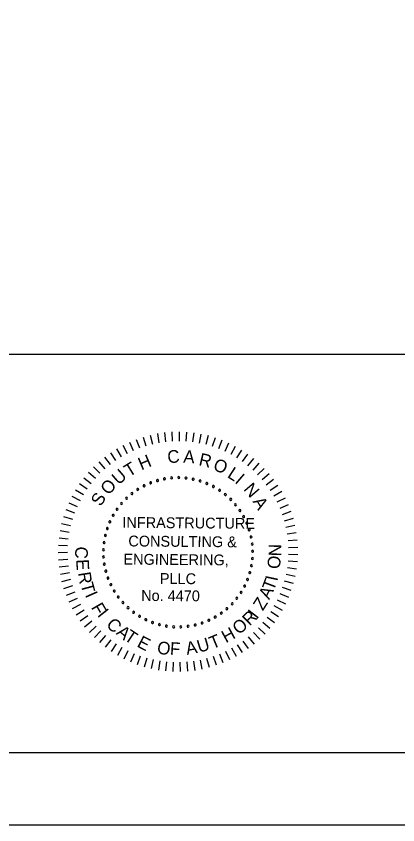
# Model space of a CAD drawing. Extents: x -121.2 to -24.9, y 6.4 to 65.9.
# Drawn here: x -53.92 to -46.89, y 6.35 to 21.24 of the extents above; entities that cross this region are included whole.
import ezdxf

# ---------------------------------------------------------------- set-up
doc = ezdxf.new("R2010")
doc.units = 0
for name, color, linetype in [('BR_BORDER LINES', 7, 'Continuous'), ('BR_TEXT', 7, 'Continuous'), ('Level 31', 7, 'Continuous')]:
    doc.layers.add(name, color=color, linetype=linetype)

msp = doc.modelspace()

# ---------------------------------------------------------------- linework, layer by layer
at = {"layer": 'BR_BORDER LINES'}
for p, q in [((-60.804, 15.017), (-46.496, 15.017)), ((-116.272, 7.683), (-26.496, 7.683))]:
    msp.add_line(p, q, dxfattribs=at)
at = {"layer": 'BR_TEXT'}
for p, q in [((-51.321, 13.553), (-51.292, 13.386)), ((-51.188, 13.572), (-51.169, 13.403)), ((-51.054, 13.583), (-51.045, 13.413)), ((-50.919, 13.586), (-50.921, 13.416)), ((-50.785, 13.58), (-50.796, 13.411)), ((-50.651, 13.567), (-50.673, 13.399)), ((-51.711, 13.447), (-51.651, 13.288)), ((-51.583, 13.49), (-51.533, 13.328)), ((-51.453, 13.526), (-51.413, 13.36)), ((-50.518, 13.545), (-50.55, 13.378)), ((-50.387, 13.515), (-50.429, 13.351)), ((-50.257, 13.478), (-50.31, 13.316)), ((-50.131, 13.432), (-50.193, 13.274)), ((-52.074, 13.272), (-51.987, 13.127)), ((-51.957, 13.338), (-51.878, 13.187)), ((-51.835, 13.396), (-51.766, 13.241)), ((-50.007, 13.379), (-50.079, 13.225)), ((-49.887, 13.318), (-49.968, 13.169)), ((-49.77, 13.251), (-49.86, 13.106)), ((-52.296, 13.12), (-52.192, 12.986)), ((-52.187, 13.2), (-52.091, 13.06)), ((-49.659, 13.176), (-49.757, 13.037)), ((-52.4, 13.034), (-52.287, 12.907)), ((-49.551, 13.094), (-49.658, 12.962)), ((-49.449, 13.006), (-49.564, 12.881)), ((-52.59, 12.844), (-52.463, 12.732)), ((-52.498, 12.942), (-52.378, 12.822)), ((-49.353, 12.913), (-49.475, 12.794)), ((-49.262, 12.813), (-49.391, 12.702)), ((-52.677, 12.741), (-52.543, 12.636)), ((-49.178, 12.708), (-49.313, 12.606)), ((-52.83, 12.52), (-52.684, 12.432)), ((-52.757, 12.633), (-52.617, 12.536)), ((-49.1, 12.598), (-49.242, 12.504)), ((-52.896, 12.402), (-52.745, 12.324)), ((-49.029, 12.484), (-49.176, 12.398)), ((-48.966, 12.365), (-49.117, 12.289)), ((-52.954, 12.281), (-52.799, 12.212)), ((-48.909, 12.243), (-49.065, 12.176)), ((-53.006, 12.157), (-52.847, 12.097)), ((-48.86, 12.117), (-49.02, 12.06)), ((-53.049, 12.029), (-52.887, 11.98)), ((-48.819, 11.989), (-48.982, 11.942)), ((-53.113, 11.768), (-52.946, 11.738)), ((-53.085, 11.9), (-52.92, 11.86)), ((-48.786, 11.859), (-48.951, 11.822)), ((-53.132, 11.635), (-52.964, 11.615)), ((-48.76, 11.727), (-48.928, 11.7)), ((-53.144, 11.501), (-52.974, 11.491)), ((-48.743, 11.593), (-48.912, 11.576)), ((-53.147, 11.366), (-52.978, 11.367)), ((-48.734, 11.459), (-48.904, 11.452)), ((-48.734, 11.324), (-48.903, 11.328)), ((-53.142, 11.231), (-52.973, 11.243)), ((-48.741, 11.19), (-48.91, 11.204)), ((-53.129, 11.097), (-52.961, 11.119)), ((-48.757, 11.056), (-48.925, 11.081)), ((-53.108, 10.965), (-52.941, 10.997)), ((-53.079, 10.833), (-52.914, 10.875)), ((-48.78, 10.923), (-48.947, 10.958)), ((-53.042, 10.704), (-52.88, 10.756)), ((-48.812, 10.793), (-48.976, 10.838)), ((-52.997, 10.577), (-52.838, 10.639)), ((-48.899, 10.538), (-49.056, 10.603)), ((-48.852, 10.664), (-49.013, 10.719)), ((-52.944, 10.453), (-52.79, 10.524)), ((-48.954, 10.415), (-49.107, 10.489)), ((-52.884, 10.333), (-52.734, 10.413)), ((-52.816, 10.216), (-52.672, 10.306)), ((-49.086, 10.181), (-49.229, 10.273)), ((-49.017, 10.296), (-49.165, 10.379)), ((-52.742, 10.104), (-52.603, 10.202)), ((-49.163, 10.07), (-49.3, 10.17)), ((-52.661, 9.996), (-52.529, 10.103)), ((-52.573, 9.894), (-52.448, 10.008)), ((-49.335, 9.863), (-49.459, 9.98)), ((-49.246, 9.964), (-49.376, 10.073)), ((-52.48, 9.797), (-52.362, 9.919)), ((-52.381, 9.706), (-52.27, 9.835)), ((-49.431, 9.768), (-49.547, 9.892)), ((-52.276, 9.622), (-52.173, 9.757)), ((-52.166, 9.543), (-52.072, 9.685)), ((-49.638, 9.597), (-49.738, 9.734)), ((-49.532, 9.679), (-49.64, 9.81)), ((-52.052, 9.472), (-51.967, 9.619)), ((-51.934, 9.408), (-51.858, 9.56)), ((-49.984, 9.389), (-50.058, 9.542)), ((-49.864, 9.451), (-49.947, 9.6)), ((-49.749, 9.521), (-49.841, 9.663)), ((-51.812, 9.351), (-51.745, 9.507)), ((-51.687, 9.302), (-51.629, 9.461)), ((-51.559, 9.26), (-51.511, 9.423)), ((-51.428, 9.226), (-51.391, 9.392)), ((-50.493, 9.217), (-50.528, 9.384)), ((-50.362, 9.249), (-50.407, 9.412)), ((-50.233, 9.288), (-50.288, 9.449)), ((-50.107, 9.335), (-50.171, 9.492)), ((-51.296, 9.2), (-51.269, 9.368)), ((-51.163, 9.183), (-51.146, 9.352)), ((-51.028, 9.173), (-51.022, 9.343)), ((-50.894, 9.172), (-50.898, 9.342)), ((-50.759, 9.179), (-50.773, 9.348)), ((-50.626, 9.194), (-50.65, 9.362))]:
    msp.add_line(p, q, dxfattribs=at)
for centre, start, end in [((-51.445, 12.647), 21.6807, 201.6807), ((-51.319, 12.689), 16.1422, 196.1422), ((-51.319, 12.689), 196.1422, 16.1422), ((-51.19, 12.72), 10.6038, 190.6038), ((-51.19, 12.72), 190.6038, 10.6038), ((-51.058, 12.738), 5.0653, 185.0653), ((-51.058, 12.738), 185.0653, 5.0653), ((-50.926, 12.743), 359.5268, 179.5268), ((-50.926, 12.743), 179.5268, 359.5268), ((-50.793, 12.735), 353.9884, 173.9884), ((-50.793, 12.735), 173.9884, 353.9884), ((-50.662, 12.714), 348.4499, 168.4499), ((-50.662, 12.714), 168.4499, 348.4499), ((-50.533, 12.681), 162.9114, 342.9114), ((-50.533, 12.681), 342.9114, 162.9114), ((-51.682, 12.526), 32.7576, 212.7576), ((-51.682, 12.526), 212.7576, 32.7576), ((-51.566, 12.592), 27.2191, 207.2191), ((-51.566, 12.592), 207.2191, 27.2191), ((-51.445, 12.647), 201.6807, 21.6807), ((-50.408, 12.636), 157.373, 337.373), ((-50.408, 12.636), 337.373, 157.373), ((-50.288, 12.579), 151.8345, 331.8345), ((-50.288, 12.579), 331.8345, 151.8345), ((-50.174, 12.51), 146.2961, 326.2961), ((-50.174, 12.51), 326.2961, 146.2961), ((-51.89, 12.362), 43.8345, 223.8345), ((-51.89, 12.362), 223.8345, 43.8345), ((-51.79, 12.449), 38.2961, 218.2961), ((-51.79, 12.449), 218.2961, 38.2961), ((-50.068, 12.431), 140.7576, 320.7576), ((-50.068, 12.431), 320.7576, 140.7576), ((-49.969, 12.342), 315.2191, 135.2191), ((-51.982, 12.265), 49.373, 229.373), ((-51.982, 12.265), 229.373, 49.373), ((-49.969, 12.342), 135.2191, 315.2191), ((-49.88, 12.244), 129.6807, 309.6807), ((-49.88, 12.244), 309.6807, 129.6807), ((-52.135, 12.048), 60.4499, 240.4499), ((-52.135, 12.048), 240.4499, 60.4499), ((-52.063, 12.16), 54.9114, 234.9114), ((-52.063, 12.16), 234.9114, 54.9114), ((-49.8, 12.137), 124.1422, 304.1422), ((-49.8, 12.137), 304.1422, 124.1422), ((-52.195, 11.93), 65.9884, 245.9884), ((-52.195, 11.93), 245.9884, 65.9884), ((-49.731, 12.024), 118.6038, 298.6038), ((-49.731, 12.024), 298.6038, 118.6038), ((-49.673, 11.904), 113.0653, 293.0653), ((-49.673, 11.904), 293.0653, 113.0653), ((-52.243, 11.806), 71.5268, 251.5268), ((-52.243, 11.806), 251.5268, 71.5268), ((-49.628, 11.779), 107.5268, 287.5268), ((-49.628, 11.779), 287.5268, 107.5268), ((-52.279, 11.678), 77.0653, 257.0653), ((-52.279, 11.678), 257.0653, 77.0653), ((-49.594, 11.651), 101.9884, 281.9884), ((-49.594, 11.651), 281.9884, 101.9884), ((-52.303, 11.547), 82.6038, 262.6038), ((-52.303, 11.547), 262.6038, 82.6038), ((-49.573, 11.519), 96.4499, 276.4499), ((-49.573, 11.519), 276.4499, 96.4499), ((-52.314, 11.415), 88.1422, 268.1422), ((-52.314, 11.415), 268.1422, 88.1422), ((-49.565, 11.387), 90.9114, 270.9114), ((-49.565, 11.387), 270.9114, 90.9114), ((-52.312, 11.282), 93.6807, 273.6807), ((-52.298, 11.15), 99.2191, 279.2191), ((-52.312, 11.282), 273.6807, 93.6807), ((-52.298, 11.15), 279.2191, 99.2191), ((-49.569, 11.254), 85.373, 265.373), ((-49.569, 11.254), 265.373, 85.373), ((-52.27, 11.02), 104.7576, 284.7576), ((-52.27, 11.02), 284.7576, 104.7576), ((-49.587, 11.122), 79.8345, 259.8345), ((-49.587, 11.122), 259.8345, 79.8345), ((-52.231, 10.893), 110.2961, 290.2961), ((-52.231, 10.893), 290.2961, 110.2961), ((-49.659, 10.867), 68.7576, 248.7576), ((-49.659, 10.867), 248.7576, 68.7576), ((-49.617, 10.993), 74.2961, 254.2961), ((-49.617, 10.993), 254.2961, 74.2961), ((-52.179, 10.771), 115.8345, 295.8345), ((-52.179, 10.771), 295.8345, 115.8345), ((-49.713, 10.746), 63.2191, 243.2191), ((-49.713, 10.746), 243.2191, 63.2191), ((-52.115, 10.654), 121.373, 301.373), ((-52.115, 10.654), 301.373, 121.373), ((-49.779, 10.63), 57.6807, 237.6807), ((-49.779, 10.63), 237.6807, 57.6807), ((-52.041, 10.544), 126.9114, 306.9114), ((-52.041, 10.544), 306.9114, 126.9114), ((-51.956, 10.441), 132.4499, 312.4499), ((-51.956, 10.441), 312.4499, 132.4499), ((-49.942, 10.421), 46.6038, 226.6038), ((-49.942, 10.421), 226.6038, 46.6038), ((-49.856, 10.522), 52.1422, 232.1422), ((-49.856, 10.522), 232.1422, 52.1422), ((-51.862, 10.348), 137.9884, 317.9884), ((-51.862, 10.348), 317.9884, 137.9884), ((-51.759, 10.263), 143.5268, 323.5268), ((-51.759, 10.263), 323.5268, 143.5268), ((-50.038, 10.329), 41.0653, 221.0653), ((-50.038, 10.329), 221.0653, 41.0653), ((-51.649, 10.189), 149.0653, 329.0653), ((-51.649, 10.189), 329.0653, 149.0653), ((-51.532, 10.126), 154.6038, 334.6038), ((-51.532, 10.126), 334.6038, 154.6038), ((-50.373, 10.115), 24.4499, 204.4499), ((-50.255, 10.175), 29.9884, 209.9884), ((-50.255, 10.175), 209.9884, 29.9884), ((-50.143, 10.247), 35.5268, 215.5268), ((-50.143, 10.247), 215.5268, 35.5268), ((-51.409, 10.075), 160.1422, 340.1422), ((-51.409, 10.075), 340.1422, 160.1422), ((-51.283, 10.036), 345.6807, 165.6807), ((-51.283, 10.036), 165.6807, 345.6807), ((-51.152, 10.009), 351.2191, 171.2191), ((-51.152, 10.009), 171.2191, 351.2191), ((-51.02, 9.995), 356.7576, 176.7576), ((-51.02, 9.995), 176.7576, 356.7576), ((-50.887, 9.993), 2.2961, 182.2961), ((-50.887, 9.993), 182.2961, 2.2961), ((-50.755, 10.005), 7.8345, 187.8345), ((-50.755, 10.005), 187.8345, 7.8345), ((-50.624, 10.029), 13.373, 193.373), ((-50.624, 10.029), 193.373, 13.373), ((-50.497, 10.066), 18.9114, 198.9114), ((-50.497, 10.066), 198.9114, 18.9114), ((-50.373, 10.115), 204.4499, 24.4499)]:
    msp.add_arc(centre, 0.0187, start, end, dxfattribs=at)
at = {"layer": 'Level 31'}
msp.add_lwpolyline([(-121.161, 6.35), (-25.161, 6.35), (-25.161, 65.017), (-121.161, 65.017)], close=True, dxfattribs=at)

# ---------------------------------------------------------------- texts
at = {"layer": 'BR_TEXT'}
for s, height, rotation, p in [('C', 0.233, 4.7281, (-51.127, 13.006)), ('H', 0.233, 22.7882, (-51.615, 12.874)), ('A', 0.233, 355.6981, (-50.848, 13.019)), ('R', 0.233, 346.6681, (-50.57, 12.974)), ('T', 0.233, 31.8182, (-51.841, 12.747)), ('O', 0.233, 337.638, (-50.31, 12.894)), ('U', 0.233, 40.8482, (-52.036, 12.597)), ('L', 0.233, 327.108, (-50.046, 12.759)), ('I', 0.233, 319.578, (-49.906, 12.659)), ('O', 0.233, 49.8782, (-52.215, 12.408)), ('N', 0.233, 310.548, (-49.744, 12.523)), ('S', 0.233, 58.9083, (-52.363, 12.199)), ('A', 0.233, 301.5179, (-49.57, 12.303)), ('INFRASTRUCTURE', 0.19939, 359.5268, (-51.966, 11.819)), ('CONSULTING &', 0.19939, 359.5268, (-51.856, 11.476)), ('N', 0.233, 89.2085, (-49.039, 11.293)), ('C', 0.233, 267.025, (-52.829, 11.479)), ('ENGINEERING,', 0.19939, 359.5268, (-51.946, 11.142)), ('E', 0.233, 273.025, (-52.818, 11.235)), ('O', 0.233, 83.2085, (-49.068, 11.05)), ('R', 0.233, 279.025, (-52.784, 10.989)), ('PLLC', 0.1994, 359.5268, (-51.275, 10.786)), ('T', 0.233, 69.3954, (-49.178, 10.645)), ('I', 0.233, 77.9093, (-49.11, 10.825)), ('T', 0.233, 285.025, (-52.737, 10.779)), ('I', 0.233, 293.7713, (-52.658, 10.584)), ('No. 4470', 0.1994, 359.5268, (-51.62, 10.474)), ('A', 0.233, 63.3954, (-49.26, 10.484)), ('F', 0.233, 299.7713, (-52.548, 10.355)), ('Z', 0.233, 57.3954, (-49.377, 10.28)), ('I', 0.233, 308.5268, (-52.436, 10.211)), ('R', 0.233, 44.5268, (-49.619, 10)), ('I', 0.233, 52.3339, (-49.487, 10.127)), ('C', 0.233, 314.5268, (-52.278, 10.024)), ('O', 0.233, 38.5268, (-49.823, 9.841)), ('A', 0.233, 320.5268, (-52.093, 9.868)), ('H', 0.233, 28.5268, (-50.058, 9.691)), ('T', 0.233, 326.5268, (-51.948, 9.765)), ('E', 0.233, 332.5268, (-51.712, 9.638)), ('T', 0.233, 22.5268, (-50.306, 9.58)), ('O', 0.233, 350.5268, (-51.338, 9.508)), ('F', 0.233, 356.5268, (-51.094, 9.483)), ('A', 0.233, 10.5268, (-50.775, 9.479)), ('U', 0.233, 16.5268, (-50.551, 9.515))]:
    msp.add_text(s, height=height, rotation=rotation, dxfattribs=at).set_placement(p)

doc.saveas('drawing.dxf')
